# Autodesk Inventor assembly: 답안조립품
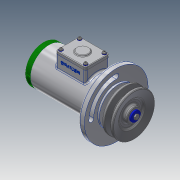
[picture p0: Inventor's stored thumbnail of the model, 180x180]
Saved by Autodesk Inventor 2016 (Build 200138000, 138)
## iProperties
Created: 2017-05
Part Number: 답안조립품
Document SubType Name: Assembly
Designer: Administrator
Author: Administrator
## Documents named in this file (20)
- D:\470507V1020\답안조립품.iam
- D:\470507V1020\1.본체.ipt
- D:\470507V1020\축.ipt
- D:\470507V1020\부시1.ipt
- D:\470507V1020\베어링 15 x 35 x 11.ipt
- D:\470507V1020\멈춤링 35x1.6.ipt
- D:\470507V1020\부시2.ipt
- D:\470507V1020\너트 M10.ipt
- D:\470507V1020\와셔 10x21.ipt
- D:\470507V1020\사이드 커버.ipt
- 사이드 커버.ipt
- D:\470507V1020\멈춤링 15 x 1.ipt
- D:\470507V1020\오일 실 15 25 7.ipt
- D:\470507V1020\키 4 x 4 x 18.ipt
- D:\470507V1020\V-벨트풀리.ipt
- D:\470507V1020\와셔 4x16.ipt
- D:\470507V1020\볼트 M4 x 10.ipt
- D:\470507V1020\탑 커버.ipt
- D:\470507V1020\와셔 3x6.ipt
- D:\470507V1020\십자볼트 M3 x 10.ipt
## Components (3 placed, 3 different names)
1. 1.본체:1 — 플러쉬:1
2. V-벨트풀리:1 — 각도:3
3. ISO 4017 M4 x 10:1
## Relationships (2: Flush 1, Angle 1)
- 플러쉬:1 [Flush]: 1.본체:1
- 각도:3 [Angle]: V-벨트풀리:1
